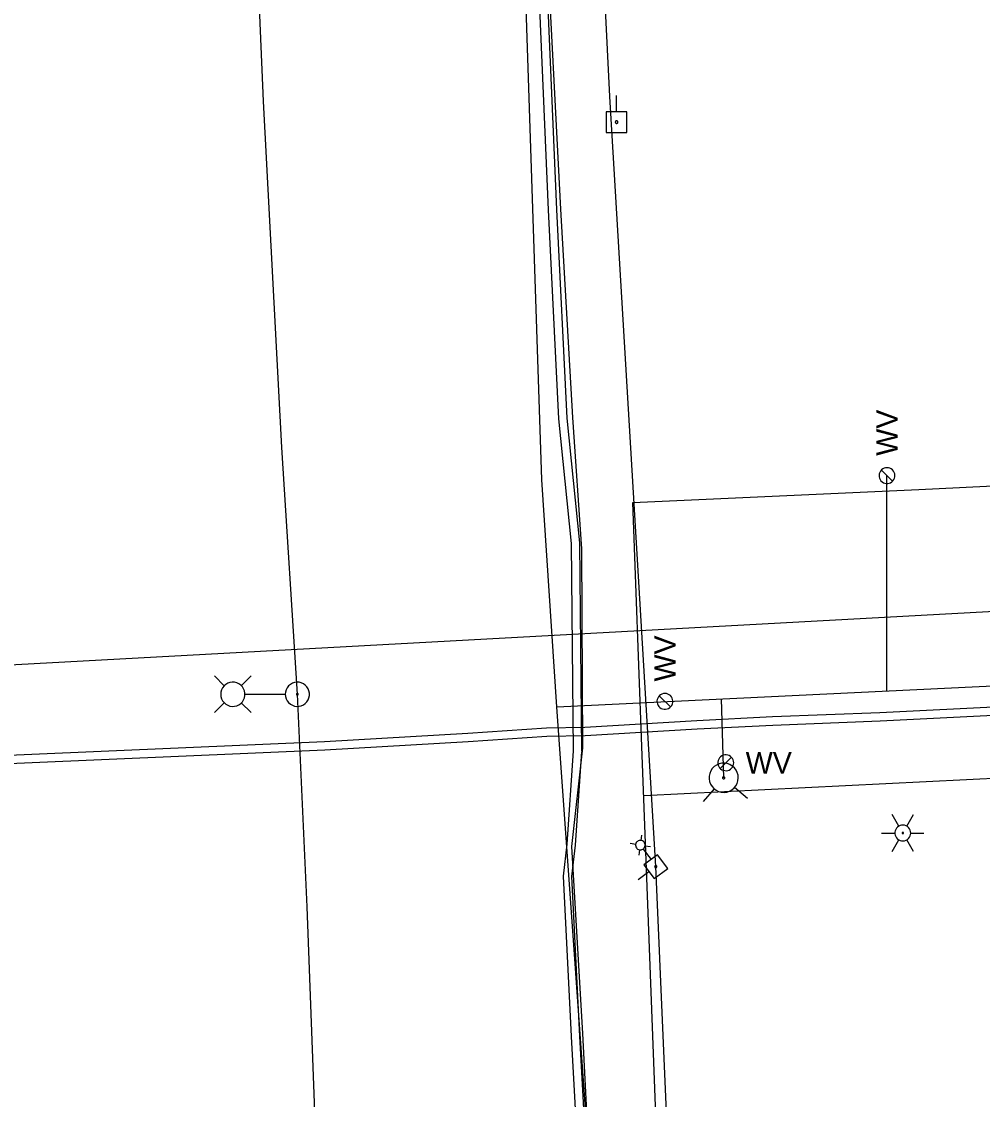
# Model space of a CAD drawing. Extents: x 596028 to 606371, y 330010 to 403088.
# Drawn here: x 604941.1 to 605113.7, y 334128.7 to 334322.4 of the extents above; entities that cross this region are included whole.
import ezdxf

# ---------------------------------------------------------------- set-up
doc = ezdxf.new("R2010")
doc.units = 0
for name, color, linetype in [('E_LTG', 7, 'Continuous'), ('E_LTG_CID', 7, 'Continuous'), ('E_UTL_EPowerPole', 7, 'Continuous'), ('E_UTL_G_UG', 7, 'Continuous'), ('E_UTL_Overhead', 7, 'Continuous'), ('E_UTL_SAN_UG', 7, 'Continuous'), ('E_UTL_W', 7, 'Continuous'), ('E_UTL_W_UG', 7, 'Continuous'), ('E_UTL_WHydrant', 7, 'Continuous')]:
    doc.layers.add(name, color=color, linetype=linetype)

msp = doc.modelspace()

# ---------------------------------------------------------------- linework, layer by layer
at = {"layer": 'E_LTG'}
for points in [[(604977.5, 334203.02), (604975.73, 334204.8)], [(604980.55, 334203.02), (604982.33, 334204.8)], [(604976.85, 334201.5), (604976.89, 334201.09), (604977.01, 334200.69), (604977.2, 334200.33), (604977.45, 334200), (604977.76, 334199.73), (604978.12, 334199.52), (604978.51, 334199.39), (604978.92, 334199.33), (604979.34, 334199.35), (604979.74, 334199.45), (604980.11, 334199.62), (604980.45, 334199.86), (604980.74, 334200.16), (604980.96, 334200.5), (604981.11, 334200.89), (604981.19, 334201.29), (604981.19, 334201.71), (604981.11, 334202.11), (604980.96, 334202.5), (604980.74, 334202.85), (604980.45, 334203.15), (604980.11, 334203.39), (604979.74, 334203.56), (604979.34, 334203.66), (604978.92, 334203.67), (604978.51, 334203.62), (604978.12, 334203.48), (604977.76, 334203.27), (604977.45, 334203), (604977.2, 334202.68), (604977.01, 334202.31), (604976.89, 334201.91), (604976.85, 334201.5)], [(604988.45, 334201.5), (604988.49, 334201.09), (604988.61, 334200.69), (604988.8, 334200.33), (604989.06, 334200), (604989.37, 334199.73), (604989.73, 334199.52), (604990.12, 334199.39), (604990.53, 334199.33), (604990.94, 334199.35), (604991.34, 334199.45), (604991.72, 334199.62), (604992.05, 334199.86), (604992.34, 334200.16), (604992.56, 334200.5), (604992.72, 334200.89), (604992.8, 334201.29), (604992.8, 334201.71), (604992.72, 334202.11), (604992.56, 334202.5), (604992.34, 334202.85), (604992.05, 334203.15), (604991.72, 334203.39), (604991.34, 334203.56), (604990.94, 334203.66), (604990.53, 334203.67), (604990.12, 334203.62), (604989.73, 334203.48), (604989.37, 334203.27), (604989.06, 334203), (604988.8, 334202.68), (604988.61, 334202.31), (604988.49, 334201.91), (604988.45, 334201.5)], [(604977.5, 334199.98), (604975.73, 334198.2)], [(604980.55, 334199.98), (604982.33, 334198.2)], [(604981.24, 334201.5), (604988.42, 334201.5)], [(604990.46, 334201.5), (604990.47, 334201.47), (604990.48, 334201.44), (604990.49, 334201.41), (604990.51, 334201.39), (604990.53, 334201.37), (604990.56, 334201.35), (604990.59, 334201.34), (604990.62, 334201.34), (604990.65, 334201.34), (604990.68, 334201.34), (604990.71, 334201.36), (604990.74, 334201.38), (604990.76, 334201.4), (604990.78, 334201.43), (604990.79, 334201.45), (604990.8, 334201.49), (604990.8, 334201.52), (604990.79, 334201.55), (604990.78, 334201.58), (604990.76, 334201.6), (604990.74, 334201.63), (604990.71, 334201.65), (604990.68, 334201.66), (604990.65, 334201.67), (604990.62, 334201.67), (604990.59, 334201.66), (604990.56, 334201.65), (604990.53, 334201.64), (604990.51, 334201.62), (604990.49, 334201.59), (604990.48, 334201.56), (604990.47, 334201.53), (604990.46, 334201.5)], [(605098.71, 334177.81), (605097.52, 334179.87)], [(605100.14, 334177.81), (605101.33, 334179.87)], [(605100.86, 334176.57), (605100.83, 334176.84), (605100.75, 334177.1), (605100.63, 334177.35), (605100.46, 334177.56), (605100.26, 334177.74), (605100.02, 334177.87), (605099.76, 334177.96), (605099.5, 334178), (605099.22, 334177.99), (605098.96, 334177.92), (605098.71, 334177.81), (605098.49, 334177.65), (605098.3, 334177.46), (605098.16, 334177.23), (605098.06, 334176.98), (605098.01, 334176.71), (605098.01, 334176.44), (605098.06, 334176.17), (605098.16, 334175.92), (605098.3, 334175.69), (605098.49, 334175.49), (605098.71, 334175.34), (605098.96, 334175.22), (605099.22, 334175.16), (605099.5, 334175.15), (605099.76, 334175.18), (605100.02, 334175.27), (605100.26, 334175.41), (605100.46, 334175.59), (605100.63, 334175.8), (605100.75, 334176.04), (605100.83, 334176.3), (605100.86, 334176.57)], [(605100.86, 334176.57), (605100.83, 334176.84), (605100.75, 334177.1), (605100.63, 334177.35), (605100.46, 334177.56), (605100.26, 334177.74), (605100.02, 334177.87), (605099.76, 334177.96), (605099.5, 334178), (605099.22, 334177.99), (605098.96, 334177.92), (605098.71, 334177.81), (605098.49, 334177.65), (605098.3, 334177.46), (605098.16, 334177.23), (605098.06, 334176.98), (605098.01, 334176.71), (605098.01, 334176.44), (605098.06, 334176.17), (605098.16, 334175.92), (605098.3, 334175.69), (605098.49, 334175.49), (605098.71, 334175.34), (605098.96, 334175.22), (605099.22, 334175.16), (605099.5, 334175.15), (605099.76, 334175.18), (605100.02, 334175.27), (605100.26, 334175.41), (605100.46, 334175.59), (605100.63, 334175.8), (605100.75, 334176.04), (605100.83, 334176.3), (605100.86, 334176.57)], [(605100.86, 334176.57), (605100.83, 334176.84), (605100.75, 334177.1), (605100.63, 334177.35), (605100.46, 334177.56), (605100.26, 334177.74), (605100.02, 334177.87), (605099.76, 334177.96), (605099.5, 334178), (605099.22, 334177.99), (605098.96, 334177.92), (605098.71, 334177.81), (605098.49, 334177.65), (605098.3, 334177.46), (605098.16, 334177.23), (605098.06, 334176.98), (605098.01, 334176.71), (605098.01, 334176.44), (605098.06, 334176.17), (605098.16, 334175.92), (605098.3, 334175.69), (605098.49, 334175.49), (605098.71, 334175.34), (605098.96, 334175.22), (605099.22, 334175.16), (605099.5, 334175.15), (605099.76, 334175.18), (605100.02, 334175.27), (605100.26, 334175.41), (605100.46, 334175.59), (605100.63, 334175.8), (605100.75, 334176.04), (605100.83, 334176.3), (605100.86, 334176.57)], [(605099.55, 334176.57), (605099.54, 334176.6), (605099.54, 334176.62), (605099.53, 334176.64), (605099.51, 334176.66), (605099.5, 334176.67), (605099.48, 334176.68), (605099.46, 334176.69), (605099.43, 334176.69), (605099.41, 334176.69), (605099.39, 334176.69), (605099.37, 334176.68), (605099.35, 334176.66), (605099.33, 334176.65), (605099.32, 334176.63), (605099.31, 334176.61), (605099.31, 334176.58), (605099.31, 334176.56), (605099.31, 334176.54), (605099.32, 334176.52), (605099.33, 334176.5), (605099.35, 334176.48), (605099.37, 334176.47), (605099.39, 334176.46), (605099.41, 334176.46), (605099.43, 334176.45), (605099.46, 334176.46), (605099.48, 334176.46), (605099.5, 334176.48), (605099.51, 334176.49), (605099.53, 334176.51), (605099.54, 334176.53), (605099.54, 334176.55), (605099.55, 334176.57)], [(605051.76, 334175.07), (605051.64, 334174.97), (605051.54, 334174.84), (605051.47, 334174.69), (605051.42, 334174.53), (605051.41, 334174.37), (605051.43, 334174.21), (605051.48, 334174.06), (605051.56, 334173.91), (605051.66, 334173.79), (605051.78, 334173.68), (605051.93, 334173.61), (605052.08, 334173.56), (605052.24, 334173.54), (605052.4, 334173.55), (605052.56, 334173.59), (605052.71, 334173.66), (605052.84, 334173.75), (605052.95, 334173.87), (605053.03, 334174.01), (605053.09, 334174.16), (605053.12, 334174.32), (605053.11, 334174.49), (605053.08, 334174.65), (605053.02, 334174.8), (605052.93, 334174.93), (605052.81, 334175.05), (605052.68, 334175.14), (605052.53, 334175.2), (605052.37, 334175.24), (605052.21, 334175.24), (605052.05, 334175.21), (605051.9, 334175.16), (605051.76, 334175.07)], [(605052.39, 334175.23), (605052.53, 334176.2)], [(605095.62, 334176.57), (605098, 334176.57)], [(605097.52, 334173.27), (605098.71, 334175.34)], [(605101.33, 334173.27), (605100.14, 334175.34)], [(605100.86, 334176.57), (605103.24, 334176.57)], [(605051.43, 334174.51), (605050.45, 334174.66)], [(605052.14, 334173.55), (605052, 334172.58)], [(605052.78, 334173.69), (605054.19, 334171.8)], [(605053.1, 334174.27), (605054.08, 334174.12)]]:
    msp.add_lwpolyline(points, dxfattribs=at)
at = {"layer": 'E_LTG_CID'}
msp.add_lwpolyline([(605017.72, 333545.18), (605018.86, 333593.18), (605019.31, 333619.04), (605019.11, 333662.74), (605017.7, 333668.32), (605017.29, 333684.65), (605016.2, 333704.19), (605012.52, 333714.35), (605010.86, 333742.99), (605009.02, 333796.81), (605006.86, 333832.68), (605008.56, 333838.78), (605005.64, 333851.75), (605010.35, 333891.22), (605002.22, 333986.67), (604999.56, 334013), (604995.2, 334088.09), (604992.37, 334163.31), (604990.63, 334201.5), (604987.81, 334245.82), (604984.57, 334308.11), (604981.59, 334376.96)], dxfattribs=at)
at = {"layer": 'E_UTL_EPowerPole'}
for points in [[(605047.98, 334306.17), (605047.98, 334309.08)], [(605049.82, 334306.17), (605046.13, 334306.17)], [(605046.13, 334306.17), (605046.13, 334302.48)], [(605048.25, 334304.33), (605048.24, 334304.37), (605048.23, 334304.42), (605048.21, 334304.46), (605048.18, 334304.49), (605048.15, 334304.52), (605048.11, 334304.54), (605048.07, 334304.56), (605048.02, 334304.57), (605047.98, 334304.56), (605047.93, 334304.55), (605047.89, 334304.53), (605047.85, 334304.51), (605047.82, 334304.48), (605047.8, 334304.44), (605047.78, 334304.4), (605047.77, 334304.35), (605047.77, 334304.31), (605047.78, 334304.26), (605047.8, 334304.22), (605047.82, 334304.18), (605047.85, 334304.15), (605047.89, 334304.12), (605047.93, 334304.1), (605047.98, 334304.09), (605048.02, 334304.09), (605048.07, 334304.1), (605048.11, 334304.11), (605048.15, 334304.13), (605048.18, 334304.16), (605048.21, 334304.2), (605048.23, 334304.24), (605048.24, 334304.28), (605048.25, 334304.33)], [(605049.82, 334302.48), (605049.82, 334306.17)], [(605046.13, 334302.48), (605049.82, 334302.48)], [(605055.37, 334172.67), (605052.9, 334170.84)], [(605052.9, 334170.84), (605054.73, 334168.37)], [(605057.2, 334170.2), (605055.37, 334172.67)], [(605053.81, 334169.6), (605051.87, 334168.16)], [(605054.73, 334168.37), (605057.2, 334170.2)], [(605054.91, 334170.7), (605054.88, 334170.67), (605054.86, 334170.64), (605054.85, 334170.61), (605054.84, 334170.57), (605054.83, 334170.54), (605054.84, 334170.5), (605054.85, 334170.46), (605054.87, 334170.43), (605054.89, 334170.4), (605054.92, 334170.38), (605054.95, 334170.36), (605054.99, 334170.35), (605055.03, 334170.34), (605055.06, 334170.34), (605055.1, 334170.35), (605055.13, 334170.37), (605055.16, 334170.39), (605055.19, 334170.42), (605055.21, 334170.45), (605055.22, 334170.49), (605055.23, 334170.52), (605055.23, 334170.56), (605055.22, 334170.6), (605055.21, 334170.63), (605055.18, 334170.67), (605055.16, 334170.69), (605055.13, 334170.71), (605055.09, 334170.73), (605055.06, 334170.74), (605055.02, 334170.74), (605054.98, 334170.73), (605054.94, 334170.72), (605054.91, 334170.7)]]:
    msp.add_lwpolyline(points, dxfattribs=at)
at = {"layer": 'E_UTL_G_UG'}
for p, q in [((605102.33, 334238.28), (605290.02, 334247.49)), ((605095.32, 334198.25), (605290.47, 334207.64)), ((605095.39, 334196.75), (605290.54, 334206.14)), ((605052.89, 334183.33), (605293.1, 334195.11))]:
    msp.add_line(p, q, dxfattribs=at)
for points in [[(605040.23, 334191.32), (605039.92, 334228.6), (605037.6, 334251), (605035.78, 334288.54), (605033.99, 334330.42), (605029.72, 334400.72), (605027, 334461.53), (605025.04, 334502.92), (605022.08, 334562.25), (605019.16, 334619.47), (605016.73, 334688.85), (605013.32, 334719.29), (605013.33, 334743.69)], [(605041.73, 334191.33), (605041.42, 334228.69), (605039.1, 334251.12), (605037.28, 334288.61), (605035.49, 334330.5), (605031.22, 334400.8), (605028.5, 334461.6), (605026.54, 334502.99), (605023.58, 334562.33), (605020.66, 334619.54), (605018.23, 334688.96), (605014.82, 334719.37), (605014.83, 334743.69)], [(605051.05, 333995.08), (605049.47, 334015.72), (605046.07, 334056.96), (605044.47, 334091.26), (605041.93, 334140.57), (605039.98, 334174.15), (605041.91, 334191.85), (605041.77, 334227.61), (605040.14, 334251.24), (605037.95, 334288.67), (605035.85, 334330.32), (605032.15, 334401.1), (605029.33, 334461.67), (605027.31, 334503.35), (605024.31, 334562.57), (605021.46, 334619.32), (605018.89, 334689.8), (605016.63, 334727.49)], [(605068.25, 333992.48), (605059.79, 333991.71), (605059.67, 334004.67), (605058.03, 334047.15), (605052.56, 334192.1), (605050.91, 334235.94), (605102.33, 334238.28)], [(604877.78, 334187.91), (604995.48, 334193.01), (605021.24, 334194.51), (605035.38, 334195.48), (605042.27, 334195.61), (605062.39, 334196.8), (605076.03, 334197.48), (605095.32, 334198.25)], [(604877.85, 334186.41), (604995.56, 334191.51), (605021.33, 334193.01), (605035.45, 334193.98), (605042.33, 334194.11), (605062.47, 334195.3), (605076.1, 334195.98), (605095.38, 334196.75)], [(605051.05, 333995.08), (605048.19, 333995.12), (605048.12, 333996.96), (605043.86, 334057.56), (605042.59, 334091.26), (605039.9, 334140), (605038.43, 334168.81), (605039.11, 334174.54), (605040.23, 334191.32)], [(605051.07, 333996.58), (605049.63, 333996.6), (605049.62, 333997.04), (605045.36, 334057.64), (605044.09, 334091.33), (605041.4, 334140.08), (605039.93, 334168.76), (605040.6, 334174.4), (605041.73, 334191.22)]]:
    msp.add_lwpolyline(points, dxfattribs=at)
at = {"layer": 'E_UTL_Overhead'}
msp.add_lwpolyline([(605060.82, 334038.02), (605055.03, 334170.54), (605046.79, 334308.95), (605039.96, 334446.59), (605033.68, 334567.58), (605029.55, 334681.31), (605027.59, 334747.04), (605025.74, 334817.42), (605020.39, 334948.8), (605014.12, 335115.1), (605007.91, 335297.38), (604985.32, 335465.29), (604968.51, 335602.26), (604952.43, 335708.38), (604942.9, 335774.97)], dxfattribs=at)
at = {"layer": 'E_UTL_SAN_UG'}
msp.add_line((604916.64, 334205.57), (605186.48, 334220.25), dxfattribs=at)
at = {"layer": 'E_UTL_W'}
for points in [[(605096.59, 334242.22), (605096.32, 334242.19), (605096.06, 334242.12), (605095.82, 334241.99), (605095.61, 334241.82), (605095.43, 334241.62), (605095.29, 334241.38), (605095.2, 334241.13), (605095.17, 334240.86), (605095.18, 334240.59), (605095.24, 334240.33), (605095.35, 334240.08), (605095.51, 334239.86), (605095.71, 334239.67), (605095.94, 334239.52), (605096.19, 334239.42), (605096.45, 334239.37), (605096.73, 334239.37), (605096.99, 334239.42), (605097.24, 334239.52), (605097.47, 334239.67), (605097.67, 334239.86), (605097.82, 334240.08), (605097.94, 334240.33), (605098, 334240.59), (605098.01, 334240.86), (605097.98, 334241.13), (605097.89, 334241.38), (605097.75, 334241.62), (605097.57, 334241.82), (605097.36, 334241.99), (605097.12, 334242.12), (605096.86, 334242.19), (605096.59, 334242.22)], [(605097.6, 334239.78), (605095.58, 334241.8)], [(605056.67, 334201.65), (605056.4, 334201.63), (605056.14, 334201.55), (605055.9, 334201.43), (605055.69, 334201.26), (605055.51, 334201.05), (605055.38, 334200.82), (605055.29, 334200.56), (605055.25, 334200.3), (605055.26, 334200.02), (605055.33, 334199.76), (605055.44, 334199.51), (605055.6, 334199.29), (605055.79, 334199.11), (605056.02, 334198.96), (605056.27, 334198.86), (605056.54, 334198.81), (605056.81, 334198.81), (605057.08, 334198.86), (605057.33, 334198.96), (605057.56, 334199.11), (605057.75, 334199.29), (605057.91, 334199.51), (605058.02, 334199.76), (605058.09, 334200.02), (605058.1, 334200.3), (605058.06, 334200.56), (605057.97, 334200.82), (605057.84, 334201.05), (605057.66, 334201.26), (605057.45, 334201.43), (605057.2, 334201.55), (605056.94, 334201.63), (605056.67, 334201.65)], [(605057.68, 334199.22), (605055.67, 334201.24)], [(605069.06, 334189.19), (605069.03, 334189.46), (605068.96, 334189.72), (605068.83, 334189.96), (605068.66, 334190.17), (605068.46, 334190.35), (605068.22, 334190.49), (605067.97, 334190.58), (605067.7, 334190.61), (605067.43, 334190.6), (605067.17, 334190.54), (605066.92, 334190.42), (605066.7, 334190.27), (605066.51, 334190.07), (605066.36, 334189.84), (605066.26, 334189.59), (605066.21, 334189.33), (605066.21, 334189.05), (605066.26, 334188.79), (605066.36, 334188.54), (605066.51, 334188.31), (605066.7, 334188.11), (605066.92, 334187.95), (605067.17, 334187.84), (605067.43, 334187.78), (605067.7, 334187.77), (605067.97, 334187.8), (605068.22, 334187.89), (605068.46, 334188.03), (605068.66, 334188.21), (605068.83, 334188.42), (605068.96, 334188.66), (605069.03, 334188.92), (605069.06, 334189.19)], [(605066.62, 334188.18), (605068.64, 334190.2)]]:
    msp.add_lwpolyline(points, dxfattribs=at)
at = {"layer": 'E_UTL_W_UG'}
for p, q in [((605037.24, 334199.25), (605328.55, 334213.23)), ((605066.81, 334200.68), (605067.23, 334186.5))]:
    msp.add_line(p, q, dxfattribs=at)
for points in [[(605037.24, 334199.25), (605034.57, 334240.02), (605020.69, 334658.87), (605020.21, 334699.75)], [(605096.59, 334202.09), (605096.59, 334240.79)], [(605063.62, 333862.97), (605061.08, 333905.73), (605053.48, 334001.96), (605049.44, 334030.42), (605044.03, 334104.39), (605037.24, 334199.25)]]:
    msp.add_lwpolyline(points, dxfattribs=at)
at = {"layer": 'E_UTL_WHydrant'}
for points in [[(605064.62, 334186.29), (605064.71, 334185.8), (605064.88, 334185.34), (605065.15, 334184.91), (605065.48, 334184.55), (605065.88, 334184.25), (605066.33, 334184.04), (605066.82, 334183.91), (605067.31, 334183.88), (605067.81, 334183.94), (605068.28, 334184.1), (605068.72, 334184.34), (605069.1, 334184.66), (605069.42, 334185.04), (605069.65, 334185.48), (605069.8, 334185.96), (605069.86, 334186.46), (605069.82, 334186.95), (605069.68, 334187.43), (605069.46, 334187.88), (605069.16, 334188.28), (605068.79, 334188.61), (605068.36, 334188.87), (605067.89, 334189.04), (605067.4, 334189.12), (605066.9, 334189.1), (605066.42, 334188.99), (605065.96, 334188.79), (605065.55, 334188.51), (605065.2, 334188.15), (605064.92, 334187.74), (605064.73, 334187.28), (605064.63, 334186.79), (605064.62, 334186.29)], [(605067.03, 334186.48), (605067.04, 334186.45), (605067.05, 334186.41), (605067.07, 334186.38), (605067.1, 334186.35), (605067.13, 334186.33), (605067.17, 334186.31), (605067.2, 334186.3), (605067.24, 334186.3), (605067.28, 334186.3), (605067.31, 334186.32), (605067.35, 334186.33), (605067.38, 334186.36), (605067.4, 334186.39), (605067.42, 334186.42), (605067.43, 334186.46), (605067.43, 334186.5), (605067.43, 334186.53), (605067.42, 334186.57), (605067.4, 334186.6), (605067.38, 334186.63), (605067.35, 334186.66), (605067.32, 334186.68), (605067.28, 334186.69), (605067.25, 334186.7), (605067.21, 334186.7), (605067.17, 334186.69), (605067.14, 334186.67), (605067.11, 334186.65), (605067.08, 334186.63), (605067.06, 334186.59), (605067.04, 334186.56), (605067.03, 334186.52), (605067.03, 334186.48)], [(605065.55, 334184.53), (605063.58, 334182.22)], [(605069.21, 334184.81), (605071.51, 334182.85)]]:
    msp.add_lwpolyline(points, dxfattribs=at)

# ---------------------------------------------------------------- texts
at = {"layer": 'E_UTL_W'}
for p in [(605098.51, 334244.36), (605058.6, 334203.79)]:
    msp.add_text('WV', height=3.85, rotation=90, dxfattribs=at).set_placement(p)
msp.add_text('WV', height=3.85, dxfattribs=at).set_placement((605071.2, 334187.26))

doc.saveas('drawing.dxf')
